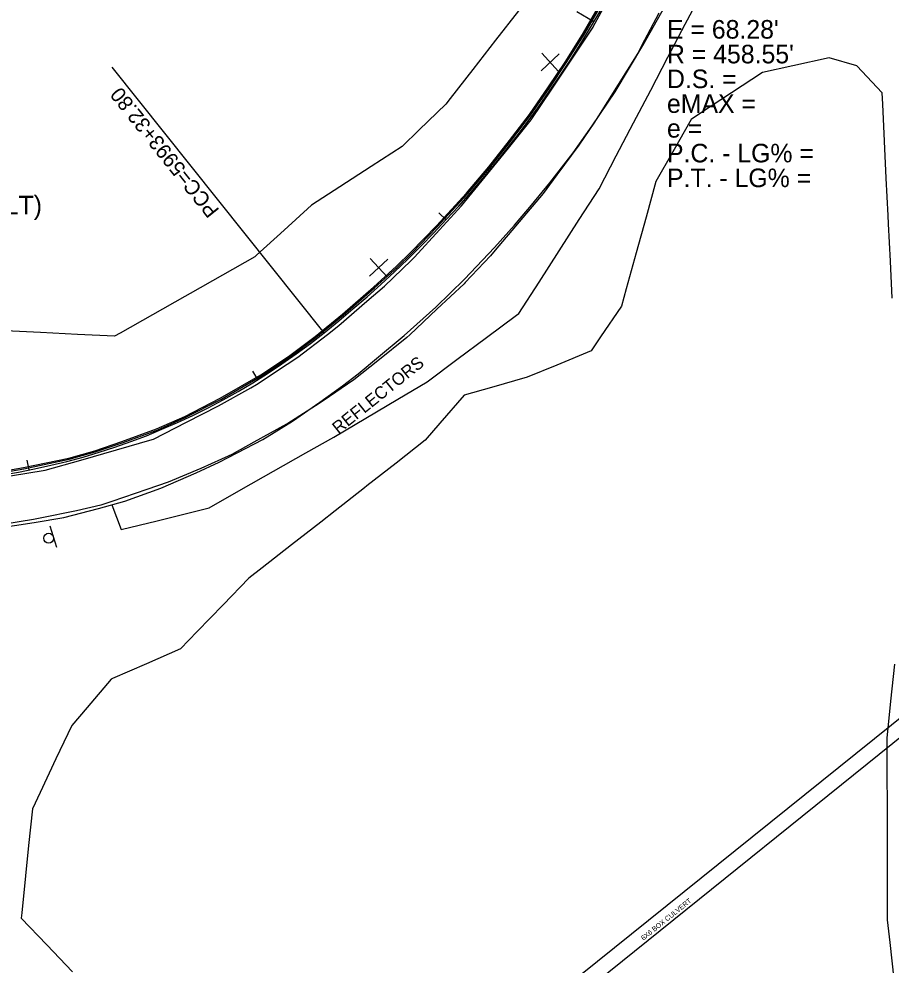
# Model space of a CAD drawing. Extents: x 2132221 to 2141942, y 535736 to 547298.
# Drawn here: x 2138576.2 to 2138928.5, y 540225.7 to 540608 of the extents above; entities that cross this region are included whole.
import ezdxf

# ---------------------------------------------------------------- set-up
doc = ezdxf.new("R2010")
doc.units = 0
for name, color, linetype in [('RD_EX_BldgApp', 7, 'Continuous'), ('RD_EX_Conc', 7, 'Continuous'), ('RD_EX_DR_Inlet_txCode', 7, 'Continuous'), ('RD_EX_Misc', 7, 'Continuous'), ('RD_EX_Misc_txCode', 7, 'Continuous'), ('RD_EX_Road', 7, 'Continuous'), ('RD_EX_VEG', 7, 'Continuous'), ('RD_HC_Cl', 7, 'Continuous'), ('RD_HC_Data', 7, 'Continuous'), ('RD_HC_Data_Tic', 7, 'Continuous')]:
    doc.layers.add(name, color=color, linetype=linetype)

msp = doc.modelspace()

# ---------------------------------------------------------------- linework, layer by layer
at = {"layer": 'RD_EX_BldgApp'}
msp.add_line((2138591.45, 540394.44), (2138588.79, 540403.04), dxfattribs=at)
msp.add_circle((2138588.18, 540398.16), 2, dxfattribs=at)
at = {"layer": 'RD_EX_Conc'}
for points in [[(2138564.93, 540424.41), (2138578.02, 540426.7), (2138596.34, 540430.55), (2138606.81, 540433.52), (2138617.7, 540437.2), (2138631.8, 540442.31), (2138643.13, 540447.36), (2138657.52, 540454.68), (2138673.88, 540464.14), (2138685.02, 540471.57), (2138695.82, 540479.61), (2138706.9, 540488.66), (2138719.48, 540499.65), (2138728.73, 540508.07), (2138734.56, 540513.72), (2138744.82, 540524.32), (2138756.99, 540537.57), (2138766.01, 540548.14), (2138774.34, 540558.78), (2138782.49, 540569.34), (2138790.19, 540580.51), (2138796.85, 540590.53), (2138804.33, 540602.33), (2138811.32, 540614.42)], [(2139012.42, 540389.97), (2138467.16, 539951.77)], [(2138471.43, 539946.97), (2139012.27, 540382.13)]]:
    msp.add_lwpolyline(points, dxfattribs=at)
at = {"layer": 'RD_EX_Misc'}
for p, q in [((2138787.1, 540587.02), (2138794.45, 540593.8)), ((2138787.39, 540594.09), (2138794.17, 540586.74)), ((2138717.83, 540504.08), (2138725.18, 540510.87)), ((2138718.11, 540511.15), (2138724.89, 540503.8))]:
    msp.add_line(p, q, dxfattribs=at)
for points in [[(2138572.77, 540423.31), (2138586.77, 540425.59), (2138601.18, 540429.76), (2138615.59, 540433.93), (2138629.99, 540438.1), (2138630.5, 540438.24), (2138643.87, 540445.04), (2138656.77, 540451.59), (2138669.83, 540458.97), (2138672.09, 540460.25), (2138684.6, 540468.53), (2138688.88, 540471.36), (2138700.77, 540480.5), (2138705.44, 540484.09), (2138716.78, 540493.91), (2138723.82, 540500), (2138734.66, 540510.37), (2138736.02, 540511.68), (2138746.14, 540522.75), (2138755.04, 540532.48), (2138764.5, 540544.12), (2138773.95, 540555.77), (2138783.18, 540567.14), (2138791.49, 540579.63), (2138799.8, 540592.12), (2138808.12, 540604.6), (2138808.18, 540604.7), (2138815.27, 540617.92)], [(2138834.76, 540610.3), (2138827.77, 540597.03), (2138826.27, 540594.17), (2138818.3, 540581.47), (2138810.32, 540568.77), (2138808.5, 540565.87), (2138802.41, 540556.98), (2138793.48, 540544.93), (2138787.96, 540537.48), (2138778.3, 540526.01), (2138768.64, 540514.53), (2138766.76, 540512.3), (2138756.42, 540501.43), (2138755.99, 540500.97), (2138745.07, 540490.68), (2138734.16, 540480.39), (2138732.89, 540479.19), (2138721.18, 540469.83), (2138711.52, 540462.11), (2138699.13, 540453.67), (2138697.47, 540452.54), (2138684.79, 540444.53), (2138684.21, 540444.17), (2138671.08, 540436.92), (2138662.18, 540432), (2138649.62, 540426.35), (2138636.42, 540420.84), (2138627.9, 540417.9), (2138613.72, 540413), (2138609.24, 540411.45), (2138599.4, 540409.24), (2138584.7, 540406.27), (2138582.08, 540405.74), (2138569.6, 540403.69)]]:
    msp.add_lwpolyline(points, dxfattribs=at)
at = {"layer": 'RD_EX_Road'}
for points in [[(2138613.66, 540411.65), (2138617.42, 540401.63), (2138631.98, 540405.25), (2138646.54, 540408.87), (2138652.96, 540410.47), (2138666.02, 540417.85), (2138679.08, 540425.23), (2138692.14, 540432.61), (2138703.46, 540439.01), (2138716.36, 540446.67), (2138729.25, 540454.33), (2138741.05, 540461.34), (2138753.08, 540470.3), (2138765.11, 540479.26), (2138777.15, 540488.22), (2138778.2, 540489), (2138786.31, 540501.62), (2138794.42, 540514.24), (2138802.53, 540526.86), (2138810.56, 540539.35), (2138817.52, 540552.64), (2138824.48, 540565.93), (2138831.44, 540579.21), (2138838.4, 540592.5), (2138845.36, 540605.79), (2138852.32, 540619.08)], [(2138565, 540423.92), (2138578.12, 540426.21), (2138596.46, 540430.06), (2138606.96, 540433.04), (2138617.86, 540436.72), (2138631.99, 540441.84), (2138643.35, 540446.91), (2138657.76, 540454.24), (2138674.14, 540463.71), (2138685.3, 540471.16), (2138696.12, 540479.22), (2138707.22, 540488.28), (2138719.82, 540499.28), (2138729.07, 540507.71), (2138734.91, 540513.36), (2138745.18, 540523.97), (2138757.36, 540537.23), (2138766.4, 540547.83), (2138774.73, 540558.47), (2138782.89, 540569.05), (2138790.6, 540580.23), (2138797.27, 540590.26), (2138804.76, 540602.08), (2138811.75, 540614.18)], [(2138556.53, 540400.55), (2138582.29, 540404.49), (2138594.32, 540406.57), (2138608.33, 540410.17), (2138619, 540413.13), (2138633.47, 540418.34), (2138647.83, 540424.53), (2138657.11, 540428.95), (2138664.38, 540432.63), (2138674.68, 540438.09), (2138686.64, 540445.39), (2138697.73, 540453.06), (2138706.86, 540459.75), (2138713.29, 540464.6), (2138721.41, 540471.48), (2138731.87, 540480.04), (2138744.64, 540491.48), (2138756.25, 540502.87), (2138768.26, 540515.55), (2138776.33, 540524.65), (2138783.27, 540532.71), (2138790.66, 540541.8), (2138800.04, 540553.91), (2138807.75, 540564.76), (2138817.02, 540578.44), (2138828.26, 540597.17), (2138837.13, 540612.95)]]:
    msp.add_lwpolyline(points, dxfattribs=at)
at = {"layer": 'RD_EX_VEG'}
for points in [[(2138778.01, 540611.23), (2138768.78, 540599.41), (2138759.56, 540587.58), (2138750.34, 540575.75), (2138748.63, 540573.56), (2138737.86, 540563.11), (2138731, 540556.45), (2138718.42, 540548.28), (2138705.85, 540540.11), (2138694.41, 540532.67), (2138683.3, 540522.59), (2138672.19, 540512.51), (2138671.44, 540511.83), (2138658.39, 540504.44), (2138645.33, 540497.05), (2138643.13, 540495.8), (2138630.07, 540488.4), (2138617.02, 540481.01), (2138614.82, 540479.76), (2138599.83, 540480.49), (2138584.85, 540481.22), (2138570.74, 540481.9)], [(2138928.98, 540495.14), (2138928.25, 540510.13), (2138927.52, 540525.11), (2138927.35, 540528.59), (2138926.62, 540543.57), (2138925.88, 540558.55), (2138925.15, 540573.54), (2138924.93, 540578.04), (2138914.76, 540589.02), (2138903.54, 540592.23), (2138888.89, 540589.03), (2138876.56, 540586.35), (2138864.03, 540578.1), (2138851.5, 540569.86), (2138847.72, 540567.37), (2138840.35, 540554.31), (2138833.56, 540542.26), (2138829.55, 540527.8), (2138825.55, 540513.4), (2138821.54, 540498.94), (2138819.58, 540491.9), (2138811.18, 540479.47), (2138807.39, 540473.85), (2138793.52, 540468.13), (2138781.48, 540463.16), (2138767.05, 540459.06), (2138756.11, 540455.94), (2138746.28, 540444.61), (2138740.35, 540437.77), (2138728.54, 540428.53), (2138716.73, 540419.28), (2138715.78, 540418.53), (2138703.96, 540409.29), (2138698.12, 540404.71), (2138686.31, 540395.46), (2138674.49, 540386.21), (2138669.1, 540381.99), (2138658.67, 540371.21), (2138648.24, 540360.43), (2138641.46, 540353.42), (2138627.69, 540347.45), (2138613.93, 540341.48), (2138613.41, 540341.26), (2138603.7, 540329.83), (2138597.52, 540322.55), (2138591.12, 540308.99), (2138584.71, 540295.42), (2138581.63, 540288.88), (2138580.08, 540273.96), (2138578.82, 540261.76), (2138577.28, 540246.84), (2138577.06, 540244.69), (2138587.45, 540233.87), (2138597.83, 540223.04)], [(2138929.73, 540219.97), (2138928.14, 540234.89), (2138927.16, 540244.02), (2138927.12, 540259.02), (2138927.09, 540274.02), (2138927.05, 540289.02), (2138927.01, 540304.02), (2138926.98, 540317.41), (2138928.49, 540332.33), (2138930, 540347.26)]]:
    msp.add_lwpolyline(points, dxfattribs=at)
at = {"layer": 'RD_HC_Cl'}
for centre, radius, start, end in [((2138413.32, 540839.47), 458.55, 308.6199, 7.6119), ((2138526.21, 540698.15), 277.68, 219.1102, 308.6199)]:
    msp.add_arc(centre, radius, start, end, dxfattribs=at)
at = {"layer": 'RD_HC_Data'}
msp.add_line((2138699.53, 540481.2), (2138613.82, 540588.49), dxfattribs=at)
at = {"layer": 'RD_HC_Data_Tic'}
for p, q in [((2138808.47, 540606.81), (2138801.58, 540610.87)), ((2138748.77, 540526.83), (2138745.85, 540529.55)), ((2138672.75, 540462.28), (2138670.64, 540465.68)), ((2138580.23, 540425.77), (2138579.45, 540429.7))]:
    msp.add_line(p, q, dxfattribs=at)

# ---------------------------------------------------------------- texts
at = {"layer": 'RD_EX_DR_Inlet_txCode'}
msp.add_text('6X6 BOX CULVERT', height=2, rotation=38.8199, dxfattribs=at).set_placement((2138828.48, 540235.53))
at = {"layer": 'RD_EX_Misc_txCode'}
msp.add_text('REFLECTORS', height=5, rotation=38.7561, dxfattribs=at).set_placement((2138705.25, 540440.01))
at = {"layer": 'RD_HC_Data'}
for s, p in [("E = 68.28'", (2138838, 540600)), ("R = 458.55'", (2138838, 540590)), ('D.S. = ', (2138838, 540580)), ('eMAX = ', (2138838, 540570)), ('e = ', (2138838, 540560)), ('P.C. - LG% = ', (2138838, 540550)), ('P.T. - LG% = ', (2138838, 540540)), ('    = 89%%d 30\' 35" (LT)', (2138496, 540529))]:
    msp.add_text(s, height=7.5, dxfattribs=at).set_placement(p)
msp.add_text('PCC=5993+32.80', height=6, rotation=128.6199, dxfattribs=at).set_placement((2138657.4, 540530.73))

doc.saveas('drawing.dxf')
